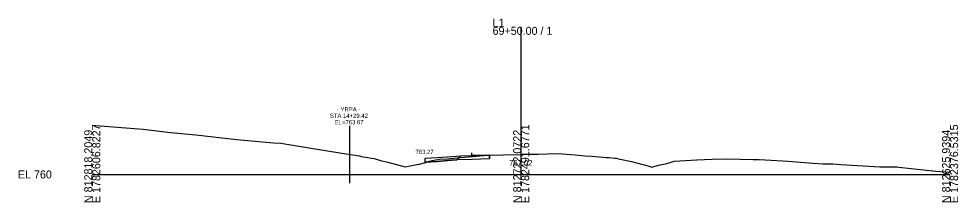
# Model space of a CAD drawing. Extents: x 5574 to 10203, y -10 to 9546.
# Drawn here: x 7574.3 to 7902.8, y 6990.3 to 7054.4 of the extents above; entities that cross this region are included whole.
import ezdxf

# ---------------------------------------------------------------- set-up
doc = ezdxf.new("R2010")
doc.units = 0
for name, color, linetype in [('Exist Cross Section Cell', 7, 'Continuous'), ('Exist XS Center Line Elevation Label', 7, 'Continuous'), ('Exist XS Ground Line', 7, 'Continuous'), ('Prop XS Ditch Standard Text', 7, 'Continuous'), ('Prop XS Dump Level', 7, 'Continuous'), ('Prop XS Earthwork Shape', 7, 'Continuous'), ('Prop XS EOT Tick Mark', 7, 'Continuous'), ('Prop XS Finish Grade', 7, 'Continuous'), ('Prop XS Finish Grade Earthwork', 7, 'Continuous'), ('Prop XS Finish Grade Paved Shoulder', 7, 'Continuous'), ('Prop XS Finish Grade Pavement', 7, 'Continuous'), ('Prop XS Hydro Typical Ditch Data', 7, 'Continuous'), ('Prop XS Pvmt Edge Slope', 7, 'Continuous'), ('Prop XS Subgrade Earthwork', 7, 'Continuous'), ('Prop XS Vertical Lines Alignments', 7, 'Continuous'), ('Scratch_Level_3', 7, 'Continuous'), ('Scratch_Level_6', 7, 'Continuous')]:
    doc.layers.add(name, color=color, linetype=linetype)

msp = doc.modelspace()

# ---------------------------------------------------------------- linework, layer by layer
at = {"layer": 'Exist Cross Section Cell'}
for p, q in [((7750, 7000), (7750, 7051.6)), ((7600, 7000), (7750, 7000)), ((7750, 7000), (7900, 7000))]:
    msp.add_line(p, q, dxfattribs=at)
at = {"layer": 'Exist XS Ground Line'}
for p, q in [((7600, 7017.2), (7601.25, 7017.12)), ((7601.25, 7017.12), (7617.75, 7015.82)), ((7617.75, 7015.82), (7627.41, 7014.66)), ((7627.41, 7014.66), (7636.2, 7013.85)), ((7636.2, 7013.85), (7650.51, 7012.23)), ((7650.51, 7012.23), (7663.42, 7011)), ((7663.42, 7011), (7665.97, 7010.89)), ((7665.97, 7010.89), (7669.44, 7010.4)), ((7669.44, 7010.4), (7687.28, 7007.44)), ((7687.28, 7007.44), (7693.49, 7006.47)), ((7693.49, 7006.47), (7694.11, 7006.33)), ((7694.11, 7006.33), (7696.41, 7005.92)), ((7696.41, 7005.92), (7697.64, 7005.74)), ((7697.64, 7005.74), (7698.57, 7005.54)), ((7698.57, 7005.54), (7700.79, 7004.93)), ((7700.79, 7004.93), (7703.34, 7004.24)), ((7715.3, 7003.81), (7718.9, 7004.87)), ((7718.9, 7004.87), (7721.38, 7005.37)), ((7721.38, 7005.37), (7724.23, 7005.47)), ((7724.23, 7005.47), (7727.47, 7005.83)), ((7727.47, 7005.83), (7730.18, 7006.06)), ((7730.18, 7006.06), (7734.27, 7006.41)), ((7734.27, 7006.41), (7737.09, 7006.58)), ((7737.09, 7006.58), (7738.89, 7006.7)), ((7738.89, 7006.7), (7743.82, 7006.84)), ((7743.82, 7006.84), (7750, 7007.02)), ((7750, 7007.02), (7750.92, 7007.05)), ((7750.92, 7007.05), (7755.89, 7007.15)), ((7755.89, 7007.15), (7762.34, 7007.29)), ((7762.34, 7007.29), (7764.29, 7007.21)), ((7764.29, 7007.21), (7765.85, 7007.14)), ((7765.85, 7007.14), (7768.91, 7006.84)), ((7768.91, 7006.84), (7772.42, 7006.55)), ((7772.42, 7006.55), (7774.69, 7006.4)), ((7774.69, 7006.4), (7778.52, 7006.09)), ((7778.52, 7006.09), (7779.75, 7005.97)), ((7779.75, 7005.97), (7780.81, 7005.87)), ((7780.81, 7005.87), (7782.81, 7005.66)), ((7782.81, 7005.66), (7783.2, 7005.64)), ((7783.2, 7005.64), (7784, 7005.48)), ((7784, 7005.48), (7788.56, 7004.53)), ((7788.56, 7004.53), (7790.33, 7004.05)), ((7801.79, 7004.09), (7803.52, 7004.62)), ((7803.52, 7004.62), (7805.5, 7004.72)), ((7805.5, 7004.72), (7811.47, 7005.08)), ((7811.47, 7005.08), (7816.81, 7005.31)), ((7816.81, 7005.31), (7821.99, 7005.48)), ((7821.99, 7005.48), (7831.16, 7005.22)), ((7831.16, 7005.22), (7832.74, 7005.26)), ((7832.74, 7005.26), (7833.23, 7005.19)), ((7833.23, 7005.19), (7835.38, 7005.08)), ((7835.38, 7005.08), (7843.36, 7004.7)), ((7843.36, 7004.7), (7851.95, 7003.97)), ((7703.34, 7004.24), (7709.42, 7002.69)), ((7709.42, 7002.69), (7714.15, 7003.56)), ((7714.15, 7003.56), (7714.45, 7003.62)), ((7714.45, 7003.62), (7715.3, 7003.81)), ((7790.33, 7004.05), (7792.96, 7003.4)), ((7792.96, 7003.4), (7794.74, 7002.88)), ((7794.74, 7002.88), (7795.73, 7002.59)), ((7795.73, 7002.59), (7796.44, 7002.75)), ((7796.44, 7002.75), (7798.65, 7003.38)), ((7798.65, 7003.38), (7800.52, 7003.75)), ((7800.52, 7003.75), (7801.79, 7004.09)), ((7851.95, 7003.97), (7855.63, 7003.74)), ((7855.63, 7003.74), (7859.01, 7003.77)), ((7859.01, 7003.77), (7861.75, 7003.51)), ((7861.75, 7003.51), (7875.45, 7002.66)), ((7875.45, 7002.66), (7876.06, 7002.65)), ((7876.06, 7002.65), (7881.51, 7002.65)), ((7881.51, 7002.65), (7882.05, 7002.58)), ((7882.05, 7002.58), (7895.04, 7001.14)), ((7895.04, 7001.14), (7896.66, 7000.98)), ((7896.66, 7000.98), (7898.56, 7000.89)), ((7898.56, 7000.89), (7900, 7000.81))]:
    msp.add_line(p, q, dxfattribs=at)
at = {"layer": 'Prop XS Dump Level'}
msp.add_line((7738.86, 7006.8), (7732.77, 7006.68), dxfattribs=at)
msp.add_line((7738.86, 7006.8), (7732.77, 7006.68), dxfattribs=at)
at = {"layer": 'Prop XS Earthwork Shape'}
for points in [[(7716.36, 7004.35), (7716.36, 7004.12), (7717.31, 7004.4)], [(7727.49, 7005.12), (7725.64, 7004.98), (7720.64, 7004.58), (7717.31, 7004.4), (7718.9, 7004.87), (7721.38, 7005.37), (7724.23, 7005.47), (7727.47, 7005.83), (7730.18, 7006.06), (7734.27, 7006.41), (7737.09, 7006.58), (7738.9, 7006.7), (7738.9, 7005.45), (7732.81, 7005.28)]]:
    msp.add_lwpolyline(points, close=True, dxfattribs=at)
at = {"layer": 'Prop XS EOT Tick Mark'}
msp.add_line((7732.77, 7006.52), (7732.77, 7007.52), dxfattribs=at)
at = {"layer": 'Prop XS Finish Grade'}
for p, q in [((7720.77, 7005.77), (7716.36, 7005.6)), ((7716.36, 7005.6), (7716.36, 7004.35)), ((7725.77, 7006.17), (7720.77, 7005.77)), ((7728.77, 7006.41), (7725.77, 7006.17))]:
    msp.add_line(p, q, dxfattribs=at)
at = {"layer": 'Prop XS Finish Grade Earthwork'}
msp.add_line((7716.36, 7004.35), (7716.36, 7004.12), dxfattribs=at)
at = {"layer": 'Prop XS Finish Grade Paved Shoulder'}
msp.add_line((7732.77, 7006.52), (7728.77, 7006.41), dxfattribs=at)
at = {"layer": 'Prop XS Finish Grade Pavement'}
msp.add_line((7738.9, 7006.7), (7732.77, 7006.52), dxfattribs=at)
at = {"layer": 'Prop XS Hydro Typical Ditch Data'}
msp.add_line((7720.77, 7005.77), (7716.36, 7005.6), dxfattribs=at)
at = {"layer": 'Prop XS Pvmt Edge Slope'}
msp.add_line((7728.77, 7006.41), (7727.49, 7005.12), dxfattribs=at)
at = {"layer": 'Prop XS Subgrade Earthwork'}
for p, q in [((7720.64, 7004.58), (7716.36, 7004.35)), ((7725.64, 7004.98), (7720.64, 7004.58)), ((7727.49, 7005.12), (7725.64, 7004.98)), ((7732.81, 7005.28), (7727.49, 7005.12)), ((7738.9, 7005.45), (7732.81, 7005.28)), ((7738.9, 7005.45), (7738.9, 7006.7))]:
    msp.add_line(p, q, dxfattribs=at)
at = {"layer": 'Prop XS Vertical Lines Alignments'}
msp.add_line((7690, 7017.02), (7690, 6997.01), dxfattribs=at)
at = {"layer": 'Scratch_Level_3'}
for p, q in [((7720.77, 7005.77), (7716.36, 7005.6)), ((7716.36, 7005.6), (7716.36, 7004.35)), ((7716.36, 7004.35), (7720.64, 7004.58)), ((7720.64, 7004.58), (7725.64, 7004.98)), ((7725.77, 7006.17), (7720.77, 7005.77)), ((7725.64, 7004.98), (7727.49, 7005.12)), ((7728.77, 7006.41), (7725.77, 7006.17)), ((7727.49, 7005.12), (7728.77, 7006.41))]:
    msp.add_line(p, q, dxfattribs=at)
at = {"layer": 'Scratch_Level_6'}
msp.add_lwpolyline([(7727.49, 7005.12), (7725.64, 7004.98), (7720.64, 7004.58), (7717.31, 7004.4), (7718.9, 7004.87), (7721.38, 7005.37), (7724.23, 7005.47), (7727.47, 7005.83), (7730.18, 7006.06), (7734.27, 7006.41), (7737.09, 7006.58), (7738.9, 7006.7), (7738.9, 7005.45), (7732.81, 7005.28)], close=True, dxfattribs=at)

# ---------------------------------------------------------------- texts
at = {"layer": 'Exist Cross Section Cell'}
for s, p in [('L1', (7740, 7051.6)), ('69+50.00 / 1', (7740, 7048.8)), ('EL 760', (7574, 6998.6))]:
    msp.add_text(s, height=2.8, dxfattribs=at).set_placement(p)
for s, p in [('N 812818.2049', (7600, 6990)), ('E 1782606.8227', (7602.8, 6990)), ('N 812722.0722', (7750, 6990)), ('E 1782491.6771', (7752.8, 6990)), ('N 812625.9394', (7900, 6990)), ('E 1782376.5315', (7902.8, 6990))]:
    msp.add_text(s, height=2.8, rotation=90, dxfattribs=at).set_placement(p)
at = {"layer": 'Exist XS Center Line Elevation Label'}
msp.add_text('767.02', height=2, dxfattribs=at).set_placement((7745.79, 7003.02))
at = {"layer": 'Prop XS Ditch Standard Text'}
msp.add_text('763.27', height=1.5, dxfattribs=at).set_placement((7713.05, 7007.15))
at = {"layer": 'Prop XS Dump Level'}
for s, height, p in [('Case4', 0.04, (7720.77, 7005.73)), ('Eop', 0.3, (7738.9, 7006.4))]:
    msp.add_text(s, height=height, dxfattribs=at).set_placement(p)
at = {"layer": 'Prop XS Vertical Lines Alignments'}
for s, p in [('STA 14+29.42', (7683.1, 7019.77)), ('- YRPA -', (7685.57, 7022.02)), ('EL=763.67', (7684.81, 7017.52))]:
    msp.add_text(s, height=1.5, dxfattribs=at).set_placement(p)

doc.saveas('drawing.dxf')
